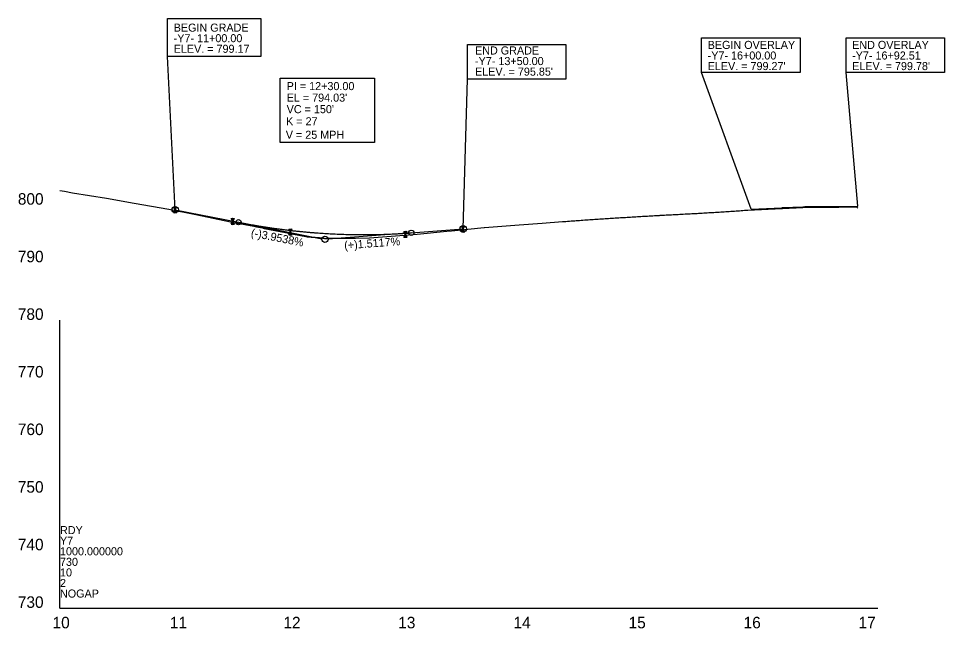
# Model space of a CAD drawing. Extents: x 579185 to 595036, y -53221 to -44640.
# Drawn here: x 587551 to 588355, y -49553 to -49023 of the extents above; entities that cross this region are included whole.
import ezdxf

# ---------------------------------------------------------------- set-up
doc = ezdxf.new("R2010")
doc.units = 0
for name, color, linetype in [('Default', 7, 'Continuous'), ('Exist Profile Cell', 7, 'Continuous'), ('Exist Vertical Profile Ground Line', 7, 'Continuous'), ('Exist Vertical Profile Horizontal Axis Label Major', 7, 'Continuous'), ('Exist Vertical Profile Vertical Axis Label', 7, 'Continuous'), ('Old_Level_2', 7, 'Continuous'), ('Prop Grid Mask', 7, 'Continuous'), ('Prop Vertical Profile Curve Label', 7, 'Continuous'), ('Prop Vertical Profile Grade', 7, 'Continuous'), ('Prop Vertical Profile Grade Label', 7, 'Continuous'), ('Prop VPI Label', 7, 'Continuous')]:
    doc.layers.add(name, color=color, linetype=linetype)

msp = doc.modelspace()

# ---------------------------------------------------------------- linework, layer by layer
at = {"layer": 'Default'}
for p, q in [((587887.47, -49210.16), (587887.47, -49209.89)), ((587887.47, -49210.52), (587887.47, -49210.16))]:
    msp.add_line(p, q, dxfattribs=at)
at = {"layer": 'Exist Profile Cell'}
for q in [(587587.47, -49285.12), (588297.47, -49535.12), (587587.47, -49535.12)]:
    msp.add_line((587587.47, -49535.12), q, dxfattribs=at)
at = {"layer": 'Exist Vertical Profile Ground Line'}
msp.add_lwpolyline([(587587.47, -49172.52), (587591.46, -49173.18), (587598.45, -49174.44), (587627.8, -49179.2), (587651.95, -49183.46), (587681.92, -49188.75), (587705.41, -49193.53), (587735.38, -49199.63), (587735.38, -49199.63), (587755.85, -49203.6), (587758.17, -49204.11), (587763.2, -49205.1), (587763.97, -49205.25), (587764.74, -49205.4), (587765.51, -49205.55), (587766.28, -49205.7), (587767.05, -49205.85), (587767.82, -49206), (587768.59, -49206.15), (587769.36, -49206.3), (587770.13, -49206.44), (587770.9, -49206.59), (587771.67, -49206.73), (587772.44, -49206.88), (587773.21, -49207.02), (587773.98, -49207.17), (587774.75, -49207.31), (587775.52, -49207.45), (587776.29, -49207.59), (587777.06, -49207.73), (587777.83, -49207.87), (587778.25, -49207.95), (587778.6, -49208.02), (587779.37, -49208.18), (587780.14, -49208.34), (587780.91, -49208.5), (587781.68, -49208.66), (587782.45, -49208.82), (587783.22, -49208.98), (587783.99, -49209.14), (587784.76, -49209.3), (587785.53, -49209.46), (587786.3, -49209.61), (587787.07, -49209.77), (587787.97, -49209.95), (587788.61, -49210.07), (587788.95, -49210.13), (587789.38, -49210.21), (587790.15, -49210.35), (587790.92, -49210.5), (587791.69, -49210.66), (587792.46, -49210.81), (587793.23, -49210.96), (587794, -49211.11), (587794.77, -49211.26), (587795.54, -49211.41), (587796.31, -49211.56), (587797.08, -49211.71), (587797.85, -49211.86), (587798.62, -49212.01), (587799.39, -49212.16), (587800.16, -49212.31), (587800.93, -49212.46), (587801.92, -49212.65), (587802.47, -49212.71), (587803.24, -49212.78), (587803.59, -49212.81), (587804.01, -49212.84), (587804.78, -49212.89), (587805.55, -49212.95), (587806.32, -49213.03), (587807.1, -49213.11), (587807.86, -49213.16), (587808.63, -49213.21), (587809.4, -49213.26), (587810.17, -49213.31), (587810.94, -49213.35), (587811.96, -49213.42), (587812.48, -49213.48), (587813.25, -49213.57), (587814.16, -49213.67), (587814.79, -49213.78), (587815.56, -49213.91), (587816.43, -49214.05), (587817.18, -49214.23), (587817.87, -49214.19), (587818.64, -49214.15), (587819.41, -49214.11), (587820.18, -49214.07), (587821.23, -49214.02), (587821.72, -49214.02), (587822.49, -49214.01), (587823.26, -49214), (587824.03, -49214), (587824.8, -49213.99), (587825.57, -49213.98), (587826.34, -49213.97), (587827.11, -49213.97), (587827.88, -49213.96), (587828.65, -49213.95), (587829.42, -49213.94), (587830.19, -49213.94), (587830.96, -49213.93), (587831.73, -49213.92), (587832.5, -49213.91), (587833.27, -49213.91), (587834.04, -49213.9), (587834.81, -49213.89), (587835.58, -49213.88), (587836.35, -49213.88), (587837.12, -49213.87), (587837.89, -49213.86), (587838.66, -49213.85), (587843.97, -49213.8), (587856.29, -49213.68), (587856.29, -49213.68), (587886.34, -49211.24), (587897.59, -49210.32), (587923.22, -49207.88), (587927.47, -49207.47), (587955.62, -49204.8), (587955.96, -49204.76), (587985.94, -49202.39), (588006.17, -49200.78), (588006.18, -49200.78), (588023.75, -49199.56), (588025.22, -49199.45), (588026.7, -49199.35), (588028.18, -49199.24), (588029.65, -49199.14), (588031.13, -49199.03), (588032.61, -49198.93), (588034.08, -49198.82), (588034.5, -49198.79), (588035.56, -49198.71), (588036.24, -49198.65), (588037.03, -49198.6), (588038.51, -49198.49), (588039.99, -49198.38), (588041.46, -49198.27), (588042.94, -49198.16), (588044.42, -49198.05), (588045.89, -49197.94), (588047.37, -49197.83), (588048.85, -49197.72), (588049.27, -49197.69), (588050.32, -49197.61), (588051.8, -49197.5), (588053.51, -49197.39), (588054.75, -49197.31), (588056.23, -49197.22), (588057.71, -49197.12), (588059.18, -49197.03), (588060.66, -49196.94), (588062.14, -49196.85), (588063.61, -49196.75), (588065.09, -49196.66), (588066.57, -49196.57), (588068.04, -49196.48), (588069.52, -49196.38), (588071, -49196.29), (588071.61, -49196.25), (588072.1, -49196.22), (588072.47, -49196.2), (588073.95, -49196.11), (588075.43, -49196.03), (588076.9, -49195.94), (588078.38, -49195.85), (588079.85, -49195.76), (588081.33, -49195.67), (588082.81, -49195.59), (588084.28, -49195.5), (588085.76, -49195.41), (588087.24, -49195.32), (588088.71, -49195.23), (588090.19, -49195.14), (588090.73, -49195.11), (588091.67, -49195.06), (588093.14, -49194.97), (588094.62, -49194.89), (588096.1, -49194.81), (588097.57, -49194.72), (588099.05, -49194.64), (588100.53, -49194.56), (588102, -49194.47), (588103.48, -49194.39), (588104.96, -49194.3), (588106.43, -49194.22), (588107.91, -49194.14), (588108.59, -49194.1), (588109.39, -49194.04), (588110.86, -49193.97), (588112.34, -49193.89), (588113.82, -49193.81), (588115.29, -49193.73), (588116.77, -49193.65), (588118.25, -49193.58), (588119.72, -49193.5), (588121.2, -49193.42), (588122.67, -49193.34), (588124.15, -49193.26), (588125.63, -49193.18), (588127.1, -49193.09), (588127.9, -49193.04), (588128.58, -49193), (588130.06, -49192.93), (588131.53, -49192.86), (588133.01, -49192.78), (588134.49, -49192.71), (588135.96, -49192.63), (588137.44, -49192.56), (588138.92, -49192.48), (588140.39, -49192.4), (588140.74, -49192.39), (588141.87, -49192.3), (588143.35, -49192.22), (588144.82, -49192.13), (588146.3, -49192.05), (588147.78, -49191.96), (588149.25, -49191.87), (588150.73, -49191.78), (588151.91, -49191.71), (588153.68, -49191.6), (588155.16, -49191.52), (588156.64, -49191.43), (588158.11, -49191.34), (588159.59, -49191.25), (588161.07, -49191.15), (588162.54, -49191.06), (588164.02, -49190.97), (588165.49, -49190.87), (588166.97, -49190.77), (588168.45, -49190.68), (588169.92, -49190.58), (588170.98, -49190.51), (588171.65, -49190.45), (588172.88, -49190.37), (588174.35, -49190.27), (588175.83, -49190.17), (588177.31, -49190.07), (588178.78, -49189.96), (588180.26, -49189.86), (588181.74, -49189.75), (588184.58, -49189.55), (588214.14, -49188.1), (588214.71, -49188.08), (588232.21, -49187.22), (588234.14, -49187.16), (588262.88, -49186.95), (588263.59, -49186.96), (588278.81, -49186.83), (588279.98, -49187.88)], dxfattribs=at)
at = {"layer": 'Old_Level_2'}
for p, q in [((587687.47, -49189.25), (587686.02, -49186.75)), ((587686.02, -49186.75), (587688.91, -49186.75)), ((587686.02, -49191.75), (587687.47, -49189.25)), ((587686.02, -49191.75), (587688.91, -49191.75)), ((587686.5, -49187.59), (587688.43, -49187.59)), ((587686.5, -49190.92), (587688.43, -49190.92)), ((587686.99, -49188.42), (587687.95, -49188.42)), ((587686.99, -49190.09), (587687.95, -49190.09)), ((587687.47, -49189.25), (587688.91, -49186.75)), ((587688.91, -49191.75), (587687.47, -49189.25)), ((587737.47, -49199.4), (587736.02, -49196.9)), ((587736.02, -49196.9), (587738.91, -49196.9)), ((587736.02, -49201.9), (587737.47, -49199.4)), ((587736.5, -49197.74), (587738.43, -49197.74)), ((587736.99, -49198.57), (587737.95, -49198.57)), ((587736.99, -49200.24), (587737.95, -49200.24)), ((587737.47, -49199.4), (587738.91, -49196.9)), ((587738.91, -49201.9), (587737.47, -49199.4)), ((587736.02, -49201.9), (587738.91, -49201.9)), ((587736.5, -49201.07), (587738.43, -49201.07)), ((587787.47, -49208.57), (587786.02, -49206.07)), ((587786.02, -49206.07), (587788.91, -49206.07)), ((587786.02, -49211.07), (587787.47, -49208.57)), ((587786.5, -49206.9), (587788.43, -49206.9)), ((587786.99, -49207.73), (587787.95, -49207.73)), ((587787.47, -49208.57), (587788.91, -49206.07)), ((587788.91, -49211.07), (587787.47, -49208.57)), ((587887.47, -49210.52), (587886.02, -49208.02)), ((587886.02, -49208.02), (587888.91, -49208.02)), ((587887.47, -49210.52), (587888.91, -49208.02)), ((587937.47, -49205.88), (587936.02, -49203.38)), ((587936.02, -49203.38), (587938.91, -49203.38)), ((587936.02, -49208.38), (587937.47, -49205.88)), ((587936.02, -49208.38), (587938.91, -49208.38)), ((587936.5, -49204.21), (587938.43, -49204.21)), ((587936.5, -49207.54), (587938.43, -49207.54)), ((587936.99, -49205.04), (587937.95, -49205.04)), ((587936.99, -49206.71), (587937.95, -49206.71)), ((587937.47, -49205.88), (587938.91, -49203.38)), ((587938.91, -49208.38), (587937.47, -49205.88)), ((587786.02, -49211.07), (587788.91, -49211.07)), ((587786.5, -49210.23), (587788.43, -49210.23)), ((587786.99, -49209.4), (587787.95, -49209.4)), ((587886.02, -49213.02), (587887.47, -49210.52)), ((587886.02, -49213.02), (587888.91, -49213.02)), ((587886.5, -49208.86), (587888.43, -49208.86)), ((587886.5, -49212.19), (587888.43, -49212.19)), ((587886.99, -49209.69), (587887.95, -49209.69)), ((587886.99, -49211.36), (587887.95, -49211.36)), ((587888.91, -49213.02), (587887.47, -49210.52))]:
    msp.add_line(p, q, dxfattribs=at)
at = {"layer": 'Prop Grid Mask'}
for points in [[(587680.76, -49023.26), (587761.82, -49023.26), (587761.82, -49056.18), (587680.76, -49056.18)], [(588144.49, -49039.94), (588229.89, -49039.94), (588229.89, -49070.13), (588144.49, -49070.13)], [(588269.89, -49039.94), (588355.28, -49039.94), (588355.28, -49070.13), (588269.89, -49070.13)], [(587941.19, -49045.75), (588026.59, -49045.75), (588026.59, -49075.94), (587941.19, -49075.94)], [(587778.55, -49074.95), (587860.36, -49074.95), (587860.36, -49130.9), (587778.55, -49130.9)]]:
    msp.add_lwpolyline(points, close=True, dxfattribs=at)
at = {"layer": 'Prop Vertical Profile Curve Label'}
for p, q in [((587687.47, -49189.25), (587680.76, -49056.18)), ((588187.47, -49188.78), (588144.49, -49070.13)), ((588279.98, -49186.2), (588269.89, -49070.13)), ((587937.47, -49205.88), (587941.19, -49075.94))]:
    msp.add_line(p, q, dxfattribs=at)
for centre in [(587742.47, -49200.12), (587892.47, -49209.28)]:
    msp.add_circle(centre, 2.25, dxfattribs=at)
at = {"layer": 'Prop Vertical Profile Grade'}
for p, q in [((587687.47, -49189.25), (587742.47, -49200.12)), ((587892.47, -49209.28), (587937.47, -49205.88))]:
    msp.add_line(p, q, dxfattribs=at)
msp.add_lwpolyline([(588187.47, -49188.78), (588214.12, -49187.47), (588214.69, -49187.45), (588232.19, -49186.6), (588234.12, -49186.53), (588262.88, -49186.33), (588263.59, -49186.33), (588279.98, -49186.2)], dxfattribs=at)
msp.add_spline([(587742.47, -49200.12), (587745.47, -49200.7), (587748.47, -49201.27), (587751.47, -49201.82), (587754.47, -49202.36), (587757.47, -49202.88), (587760.47, -49203.38), (587763.47, -49203.87), (587766.47, -49204.34), (587769.47, -49204.79), (587772.47, -49205.23), (587775.47, -49205.65), (587778.47, -49206.06), (587781.47, -49206.44), (587784.47, -49206.82), (587787.47, -49207.17), (587790.47, -49207.51), (587793.47, -49207.83), (587796.47, -49208.14), (587799.47, -49208.43), (587802.47, -49208.7), (587805.47, -49208.96), (587808.47, -49209.2), (587811.47, -49209.42), (587814.47, -49209.63), (587817.47, -49209.82), (587820.47, -49210), (587823.47, -49210.16), (587826.47, -49210.3), (587829.47, -49210.42), (587832.47, -49210.53), (587835.47, -49210.63), (587838.47, -49210.7), (587841.47, -49210.76), (587844.47, -49210.81), (587847.47, -49210.83), (587850.47, -49210.85), (587853.47, -49210.84), (587856.47, -49210.82), (587859.47, -49210.78), (587862.47, -49210.73), (587865.47, -49210.65), (587868.47, -49210.57), (587871.47, -49210.46), (587874.47, -49210.34), (587877.47, -49210.21), (587880.47, -49210.05), (587883.47, -49209.88), (587886.47, -49209.7), (587889.47, -49209.5), (587892.47, -49209.28)], degree=3, dxfattribs=at)
at = {"layer": 'Prop VPI Label'}
for p, q in [((587742.47, -49200.12), (587814.77, -49214.41)), ((587892.47, -49209.28), (587820.21, -49214.74))]:
    msp.add_line(p, q, dxfattribs=at)
for centre in [(587687.47, -49189.25), (587687.47, -49189.25), (587937.47, -49205.88), (587817.47, -49214.95)]:
    msp.add_circle(centre, 2.75, dxfattribs=at)

# ---------------------------------------------------------------- texts
at = {"layer": 'Exist Profile Cell'}
for s, p in [('RDY', (587587.47, -49470.88)), ('Y7', (587587.47, -49480.06)), ('1000.000000', (587587.47, -49489.23)), ('730', (587587.47, -49498.41)), ('10', (587587.47, -49507.59)), ('2', (587587.47, -49516.76)), ('NOGAP', (587587.47, -49525.94))]:
    msp.add_text(s, height=7, dxfattribs=at).set_placement(p)
at = {"layer": 'Exist Vertical Profile Horizontal Axis Label Major'}
for s, p in [('10', (587581.05, -49552.62)), ('11', (587682.89, -49552.62)), ('12', (587781.44, -49552.62)), ('13', (587881.11, -49552.62)), ('14', (587981.17, -49552.62)), ('15', (588081.09, -49552.62)), ('16', (588180.92, -49552.62)), ('17', (588280.66, -49552.62))]:
    msp.add_text(s, height=10, dxfattribs=at).set_placement(p)
at = {"layer": 'Exist Vertical Profile Vertical Axis Label'}
for s, p in [('800', (587550.9, -49184.87)), ('790', (587550.9, -49234.87)), ('780', (587550.9, -49284.87)), ('770', (587550.9, -49334.87)), ('760', (587550.9, -49384.87)), ('750', (587550.9, -49434.87)), ('740', (587550.9, -49484.87)), ('730', (587550.9, -49534.87))]:
    msp.add_text(s, height=10, dxfattribs=at).set_placement(p)
at = {"layer": 'Old_Level_2'}
for p in [(587687.04, -49192.76), (587687.24, -49186.59), (587737.24, -49196.74), (587737.04, -49202.91), (587787.24, -49205.91), (587887.24, -49207.86), (587937.04, -49209.38), (587937.24, -49203.22), (587787.04, -49212.07), (587887.04, -49214.03)]:
    msp.add_text('6"', height=0.8, dxfattribs=at).set_placement(p)
at = {"layer": 'Prop Vertical Profile Curve Label'}
for s, p in [("VC = 150'", (587784.24, -49105.43)), ('K = 27', (587783.74, -49115.98)), ('V = 25 MPH', (587783.48, -49127.66))]:
    msp.add_text(s, height=7, dxfattribs=at).set_placement(p)
at = {"layer": 'Prop Vertical Profile Grade Label'}
for s, rotation, p in [('(-)3.9538%', 348.81726, (587752.81, -49212.36)), ('(+)1.5117%', 4.32239, (587834.47, -49223.69))]:
    msp.add_text(s, height=7, rotation=rotation, dxfattribs=at).set_placement(p)
at = {"layer": 'Prop VPI Label'}
for s, p in [('BEGIN GRADE', (587686.17, -49034.68)), ('-Y7- 11+00.00', (587686.17, -49043.85)), ('ELEV. = 799.17', (587686.17, -49053.03)), ('END GRADE', (587947.75, -49054.51)), ('BEGIN OVERLAY', (588149.7, -49049.68)), ('END OVERLAY', (588275.1, -49049.68)), ('-Y7- 16+00.00', (588149.7, -49058.85)), ('-Y7- 16+92.51', (588275.1, -49058.85)), ('-Y7- 13+50.00', (587947.75, -49063.69)), ("ELEV. = 799.27'", (588149.7, -49068.03)), ("ELEV. = 799.78'", (588275.1, -49068.03)), ("ELEV. = 795.85'", (587947.75, -49072.87)), ('PI = 12+30.00', (587784.24, -49085.43)), ("EL = 794.03'", (587784.24, -49095.43))]:
    msp.add_text(s, height=7, dxfattribs=at).set_placement(p)

doc.saveas('drawing.dxf')
